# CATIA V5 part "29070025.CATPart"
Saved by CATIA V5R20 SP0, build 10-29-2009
Part number: 29070025
Definition: NONE
Nomenclature: 29070025
Source: Unknown
Description: 29070025
Bounding box of the stored display mesh (mm): x -12.5 to 44.548, y -49 to 83.548, z -39 to 39
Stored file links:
  C:\Users\Utente\Desktop\IO LAVORO\3D X SITO CF\X SITO\PLASTICA\RF1\29070025.CATPart
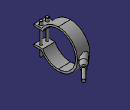
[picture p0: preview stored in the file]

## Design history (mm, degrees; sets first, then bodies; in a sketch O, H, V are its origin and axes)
Body1 "29070025" (main body)
  Solid1: solid without history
